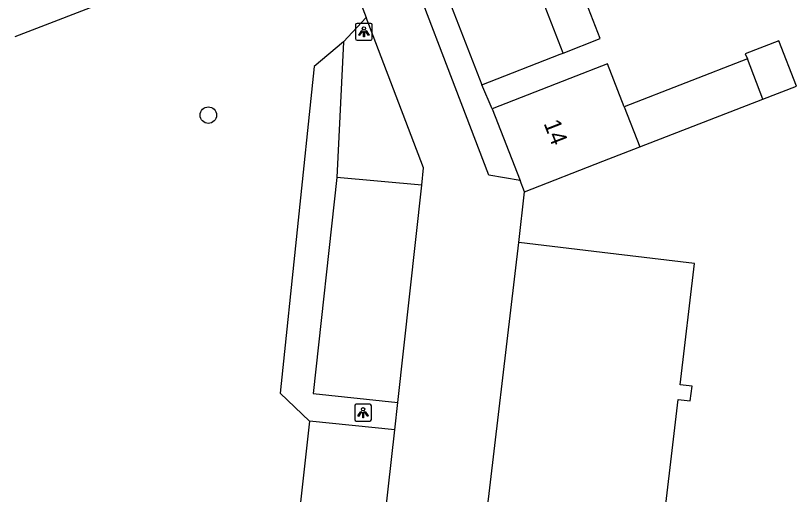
# Model space of a CAD drawing. Extents: x 161696 to 162377, y 380761 to 381673.
# Drawn here: x 161871.77 to 161918.16, y 381093.76 to 381122.22 of the extents above; entities that cross this region are included whole.
import ezdxf

# ---------------------------------------------------------------- set-up
doc = ezdxf.new("R2010")
doc.units = 0
for name, color, linetype in [('IMGEO_Boom', 7, 'Continuous'), ('IMGEO_Groenvoorziening', 7, 'Continuous'), ('IMGEO_Lichtpunt', 7, 'Continuous'), ('IMGEO_Pand', 7, 'Continuous'), ('IMGEO_Pand_nummerreeks', 7, 'Continuous'), ('IMGEO_Parkeervlak_open', 7, 'Continuous'), ('IMGEO_Rijbaan_lokaal_open', 7, 'Continuous'), ('IMGEO_Voetpad_open', 7, 'Continuous')]:
    doc.layers.add(name, color=color, linetype=linetype)

msp = doc.modelspace()

# ---------------------------------------------------------------- linework, layer by layer
at = {"layer": 'IMGEO_Boom'}
msp.add_circle((161883.222, 381116.302), 0.489, dxfattribs=at)
at = {"layer": 'IMGEO_Groenvoorziening'}
for points in [[(161892.607, 381122.097), (161891.249, 381120.655)], [(161891.249, 381120.655), (161889.509, 381119.184), (161887.481, 381099.78), (161889.237, 381098.122)], [(161891.249, 381120.655), (161890.857, 381112.602)]]:
    msp.add_lwpolyline(points, dxfattribs=at)
at = {"layer": 'IMGEO_Lichtpunt'}
for p, q in [((161891.968, 381121.66), (161891.968, 381120.853)), ((161891.968, 381121.66), (161891.968, 381120.853)), ((161892.87, 381121.755), (161892.062, 381121.755)), ((161892.87, 381121.755), (161892.062, 381121.755)), ((161892.964, 381120.853), (161892.964, 381121.66)), ((161892.964, 381120.853), (161892.964, 381121.66)), ((161892.062, 381120.759), (161892.87, 381120.759)), ((161892.062, 381120.759), (161892.87, 381120.759)), ((161892.819, 381099.118), (161892.011, 381099.118)), ((161892.819, 381099.118), (161892.011, 381099.118)), ((161891.917, 381099.023), (161891.917, 381098.216)), ((161891.917, 381099.023), (161891.917, 381098.216)), ((161892.913, 381098.216), (161892.913, 381099.023)), ((161892.913, 381098.216), (161892.913, 381099.023)), ((161892.011, 381098.122), (161892.819, 381098.122)), ((161892.011, 381098.122), (161892.819, 381098.122))]:
    msp.add_line(p, q, dxfattribs=at)
for points in [[(161892.342, 381121.324), (161892.381, 381121.296), (161892.193, 381121.034), (161892.155, 381121.061), (161892.342, 381121.324)], [(161892.444, 381121.276), (161892.491, 381121.276), (161892.491, 381120.954), (161892.444, 381120.954), (161892.444, 381121.276)], [(161892.554, 381121.296), (161892.592, 381121.323), (161892.779, 381121.061), (161892.74, 381121.033), (161892.554, 381121.296)], [(161892.291, 381098.687), (161892.33, 381098.659), (161892.142, 381098.397), (161892.104, 381098.424), (161892.291, 381098.687)], [(161892.393, 381098.639), (161892.44, 381098.639), (161892.44, 381098.317), (161892.393, 381098.317), (161892.393, 381098.639)], [(161892.503, 381098.659), (161892.541, 381098.686), (161892.728, 381098.424), (161892.689, 381098.396), (161892.503, 381098.659)]]:
    msp.add_lwpolyline(points, dxfattribs=at)
for centre in [(161892.467, 381121.458), (161892.416, 381098.821)]:
    msp.add_circle(centre, 0.0994, dxfattribs=at)
for centre, start, end in [((161892.062, 381121.66), 90, 180), ((161892.062, 381121.66), 90, 180), ((161892.87, 381121.66), 0, 90), ((161892.87, 381121.66), 0, 90), ((161892.062, 381120.853), 180, 270), ((161892.062, 381120.853), 180, 270), ((161892.87, 381120.853), 270, 0), ((161892.87, 381120.853), 270, 360), ((161892.011, 381099.023), 90, 180), ((161892.011, 381099.023), 90, 180), ((161892.819, 381099.023), 0, 90), ((161892.819, 381099.023), 0, 90), ((161892.011, 381098.216), 180, 270), ((161892.011, 381098.216), 180, 270), ((161892.819, 381098.216), 270, 0), ((161892.819, 381098.216), 270, 360)]:
    msp.add_arc(centre, 0.0946, start, end, dxfattribs=at)
at = {"layer": 'IMGEO_Pand'}
for points in [[(161899.582, 381132.126), (161894.749, 381130.245), (161899.472, 381118.111)], [(161904.304, 381119.992), (161899.582, 381132.126)], [(161904.304, 381119.992), (161906.509, 381120.85), (161904.553, 381125.877), (161906.876, 381126.781)], [(161916.175, 381117.259), (161918.162, 381118.031), (161917.116, 381120.722), (161915.114, 381119.944), (161915.249, 381119.641)], [(161899.472, 381118.111), (161904.132, 381119.925), (161904.304, 381119.992)], [(161915.249, 381119.641), (161907.935, 381116.797)], [(161916.175, 381117.259), (161915.249, 381119.641)], [(161907.935, 381116.797), (161906.94, 381119.352), (161904.692, 381118.477), (161900.087, 381116.686)], [(161908.862, 381114.414), (161916.175, 381117.259)], [(161907.935, 381116.797), (161908.862, 381114.414)], [(161900.087, 381116.686), (161901.747, 381112.421)], [(161902.009, 381111.747), (161906.669, 381113.561), (161908.862, 381114.414)], [(161902.009, 381111.747), (161901.747, 381112.421)], [(161897.356, 381072.208), (161901.665, 381108.723)], [(161897.356, 381072.208), (161902.322, 381071.622), (161907.782, 381070.978), (161911.136, 381099.407), (161911.858, 381099.322), (161911.96, 381100.185), (161911.256, 381100.268), (161912.109, 381107.49), (161906.614, 381108.139), (161901.665, 381108.723)]]:
    msp.add_lwpolyline(points, dxfattribs=at)
at = {"layer": 'IMGEO_Parkeervlak_open'}
for points in [[(161890.857, 381112.602), (161889.443, 381099.757), (161894.473, 381099.213)], [(161895.912, 381112.139), (161890.857, 381112.602)], [(161889.237, 381098.122), (161887.589, 381083.293)], [(161894.31, 381097.589), (161889.237, 381098.122)]]:
    msp.add_lwpolyline(points, dxfattribs=at)
at = {"layer": 'IMGEO_Rijbaan_lokaal_open'}
for points in [[(161901.747, 381112.421), (161899.888, 381112.731), (161893.576, 381129.276), (161890.302, 381128.132)], [(161890.302, 381128.132), (161892.607, 381122.097)], [(161895.912, 381112.139), (161896.009, 381113.169), (161892.607, 381122.097)], [(161894.473, 381099.213), (161895.912, 381112.139)], [(161901.665, 381108.723), (161902.009, 381111.747)], [(161894.31, 381097.589), (161894.473, 381099.213)], [(161892.263, 381079.432), (161894.31, 381097.589)]]:
    msp.add_lwpolyline(points, dxfattribs=at)
at = {"layer": 'IMGEO_Voetpad_open'}
for points in [[(161890.302, 381128.132), (161871.724, 381120.949)], [(161900.087, 381116.686), (161899.472, 381118.111)]]:
    msp.add_lwpolyline(points, dxfattribs=at)

# ---------------------------------------------------------------- texts
at = {"layer": 'IMGEO_Pand_nummerreeks'}
msp.add_text('14', height=1, rotation=291.2623, dxfattribs=at).set_placement((161903.13, 381115.815))

doc.saveas('drawing.dxf')
